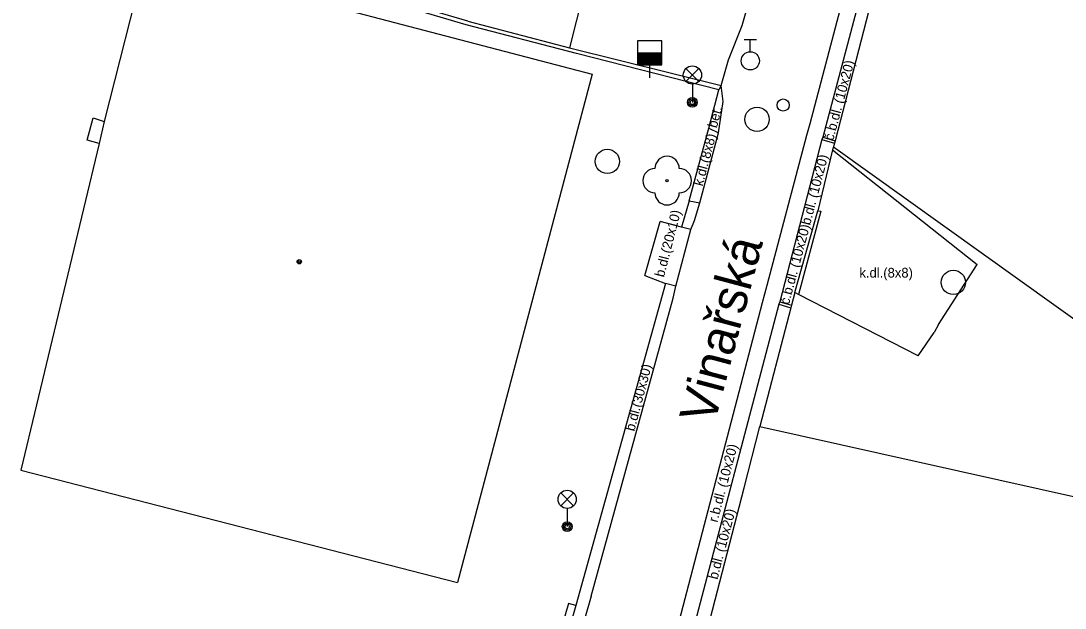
# Model space of a CAD drawing. Extents: x -600309 to -598967, y -1161267 to -1160292.
# Drawn here: x -600075.62 to -600032.67, y -1161065 to -1161040.84 of the extents above; entities that cross this region are included whole.
import ezdxf

# ---------------------------------------------------------------- set-up
doc = ezdxf.new("R2010")
doc.units = 0
for name, color, linetype in [('Level 10', 7, 'Continuous'), ('Level 11', 7, 'Continuous'), ('Level 22', 7, 'Continuous'), ('Level 24', 7, 'Continuous'), ('Level 27', 7, 'Continuous'), ('Level 28', 7, 'Continuous'), ('Level 31', 7, 'Continuous'), ('Level 33', 7, 'Continuous'), ('Level 39', 7, 'Continuous'), ('Level 40', 7, 'Continuous'), ('Level 5', 7, 'Continuous'), ('Level 50', 7, 'Continuous'), ('Level 51', 7, 'Continuous'), ('Level 7', 7, 'Continuous'), ('Level 8', 7, 'Continuous')]:
    doc.layers.add(name, color=color, linetype=linetype)

msp = doc.modelspace()

# ---------------------------------------------------------------- linework, layer by layer
at = {"layer": 'Level 10'}
for points in [[(-600049.36, -1161068.66), (-600048.8618, -1161066.7575), (-600045.11, -1161052.43), (-600044.93, -1161051.71), (-600043.29, -1161045.54), (-600043.16, -1161045.06), (-600039.19, -1161030.02), (-600039.02, -1161029.32), (-600036.88, -1161021.28), (-600036.71, -1161020.58), (-600034.3582, -1161011.7987), (-600029.87, -1160995.04), (-600029.54, -1160993.62), (-600029.33, -1160992.62)], [(-600052.17, -1161064.51), (-600048.79, -1161052.25), (-600048.68, -1161051.76), (-600048.06, -1161049.42), (-600047.92, -1161049.05), (-600047.69, -1161048.32), (-600046.93, -1161045.44), (-600046.73, -1161044.16), (-600046.82, -1161043.5), (-600046.51, -1161042.44), (-600045.95, -1161041.02), (-600045.06, -1161037.91), (-600044.82, -1161036.91)], [(-600052.17, -1161064.51), (-600054.64, -1161073.14)]]:
    msp.add_lwpolyline(points, dxfattribs=at)
at = {"layer": 'Level 11'}
for points in [[(-600028.23, -1160992.86), (-600028.68, -1160992.75), (-600028.95, -1160993.92), (-600029.25, -1160995.22), (-600036.2, -1161021.2), (-600036.23, -1161021.3), (-600038.47, -1161029.88), (-600038.5, -1161029.98), (-600042.64, -1161045.62), (-600042.67, -1161045.72), (-600044.41, -1161052.4), (-600044.44, -1161052.5), (-600048.21, -1161066.82)], [(-600057.24, -1161040.85), (-600063.37, -1161039.04), (-600073.51, -1161036.42), (-600073.55, -1161036.53)], [(-600057.24, -1161040.85), (-600053.05, -1161041.95)], [(-600053.05, -1161041.95), (-600046.82, -1161043.5)], [(-600046.82, -1161043.5), (-600046.91, -1161043.67)], [(-600072.89, -1161045.75), (-600072.65, -1161044.83)], [(-600072.65, -1161044.83), (-600072.2, -1161044.98)], [(-600047.33, -1161045.25), (-600046.93, -1161045.44)], [(-600072.4, -1161045.88), (-600072.89, -1161045.75)], [(-600042.67, -1161045.72), (-600042.16, -1161045.87)], [(-600042.64, -1161045.62), (-600042.13, -1161045.77)], [(-600042.24, -1161046.14), (-600042.84, -1161048.65)], [(-600048.13, -1161048.24), (-600047.69, -1161048.32)], [(-600048.06, -1161049.42), (-600048.45, -1161049.32)], [(-600048.68, -1161051.76), (-600049.11, -1161051.64)], [(-600044.44, -1161052.5), (-600043.95, -1161052.64)], [(-600044.41, -1161052.4), (-600043.92, -1161052.54)]]:
    msp.add_lwpolyline(points, dxfattribs=at)
at = {"layer": 'Level 22'}
msp.add_circle((-600049.04, -1161047.4099), 0.05, dxfattribs=at)
for centre, start, end in [((-600049.04, -1161046.9099), 0, 180), ((-600049.54, -1161047.4099), 90, 270), ((-600048.54, -1161047.4099), 270, 90), ((-600049.04, -1161047.9099), 180, 0)]:
    msp.add_arc(centre, 0.5, start, end, dxfattribs=at)
at = {"layer": 'Level 24'}
for points in [[(-600043.79, -1161052.02), (-600042.84, -1161048.65)], [(-600042.84, -1161048.65), (-600042.72, -1161048.67), (-600043.63, -1161052.1)]]:
    msp.add_lwpolyline(points, dxfattribs=at)
at = {"layer": 'Level 27'}
for centre in [(-600045.34, -1161044.89), (-600051.5, -1161046.62), (-600037.27, -1161051.6)]:
    msp.add_circle(centre, 0.5, dxfattribs=at)
at = {"layer": 'Level 28'}
for p, q in [((-600045.87, -1161041.605), (-600045.37, -1161041.605)), ((-600045.62, -1161042.105), (-600045.62, -1161041.605)), ((-600050.26, -1161042.15), (-600049.26, -1161042.15)), ((-600050.26, -1161042.2), (-600049.26, -1161042.2)), ((-600050.26, -1161042.25), (-600049.26, -1161042.25)), ((-600050.26, -1161042.3), (-600049.26, -1161042.3)), ((-600050.26, -1161042.35), (-600049.26, -1161042.35)), ((-600050.26, -1161042.4), (-600049.26, -1161042.4)), ((-600050.26, -1161042.45), (-600049.26, -1161042.45)), ((-600050.26, -1161042.5), (-600049.26, -1161042.5)), ((-600050.26, -1161042.55), (-600049.26, -1161042.55)), ((-600050.26, -1161042.6), (-600049.26, -1161042.6)), ((-600049.76, -1161042.65), (-600049.76, -1161043.18))]:
    msp.add_line(p, q, dxfattribs=at)
msp.add_lwpolyline([(-600050.26, -1161042.65), (-600049.26, -1161042.65), (-600049.26, -1161041.65), (-600050.26, -1161041.65)], close=True, dxfattribs=at)
msp.add_circle((-600045.62, -1161042.48), 0.375, dxfattribs=at)
at = {"layer": 'Level 31'}
msp.add_circle((-600044.27, -1161044.3), 0.25, dxfattribs=at)
at = {"layer": 'Level 33'}
for p, q in [((-600048.265, -1161043.33), (-600047.735, -1161042.8)), ((-600048.265, -1161042.8), (-600047.735, -1161043.33)), ((-600048, -1161043.44), (-600048, -1161044.19)), ((-600053.415, -1161060.79), (-600052.885, -1161060.26)), ((-600053.415, -1161060.26), (-600052.885, -1161060.79)), ((-600053.15, -1161060.9), (-600053.15, -1161061.65))]:
    msp.add_line(p, q, dxfattribs=at)
for centre, radius in [((-600048, -1161043.065), 0.375), ((-600048, -1161044.19), 0.2), ((-600048, -1161044.19), 0.1445), ((-600048, -1161044.19), 0.0876), ((-600053.15, -1161060.525), 0.375), ((-600053.15, -1161061.65), 0.2), ((-600053.15, -1161061.65), 0.1445), ((-600053.15, -1161061.65), 0.0876)]:
    msp.add_circle(centre, radius, dxfattribs=at)
at = {"layer": 'Level 39'}
for radius in [0.09, 0.0398]:
    msp.add_circle((-600064.17, -1161050.75), radius, dxfattribs=at)
at = {"layer": 'Level 5'}
for points in [[(-600070.48, -1161038.21), (-600072.2, -1161044.98)], [(-600070.48, -1161038.21), (-600052.12, -1161043.03)], [(-600052.12, -1161043.03), (-600057.6599, -1161063.95)], [(-600072.2, -1161044.98), (-600072.4, -1161045.88)], [(-600072.4, -1161045.88), (-600075.62, -1161059.32)], [(-600075.62, -1161059.32), (-600057.6599, -1161063.95)]]:
    msp.add_lwpolyline(points, dxfattribs=at)
at = {"layer": 'Level 51'}
for points in [[(-600042.2, -1161046.02), (-600026.96, -1161056.92)], [(-600045.2199, -1161057.53), (-600027.23, -1161061.55)]]:
    msp.add_lwpolyline(points, dxfattribs=at)
at = {"layer": 'Level 7'}
for points in [[(-600037.9, -1161029.49), (-600038.05, -1161029.99), (-600038.08, -1161030.09), (-600042.13, -1161045.77), (-600042.16, -1161045.87), (-600042.2, -1161046.02), (-600042.24, -1161046.14)], [(-600052.77, -1161042.18), (-600057.3, -1161041), (-600063.39, -1161039.19)], [(-600046.91, -1161043.67), (-600052.77, -1161042.18)], [(-600047.33, -1161045.25), (-600046.91, -1161043.67)], [(-600048.13, -1161048.24), (-600047.33, -1161045.25)], [(-600042.24, -1161046.14), (-600036.29, -1161050.86)], [(-600048.13, -1161048.24), (-600048.45, -1161049.32), (-600049.33, -1161049.09)], [(-600049.95, -1161051.32), (-600049.11, -1161051.64), (-600052.79, -1161064.9)], [(-600043.79, -1161052.02), (-600043.92, -1161052.54), (-600043.95, -1161052.64)], [(-600038.71, -1161054.62), (-600043.63, -1161052.1), (-600043.79, -1161052.02)], [(-600043.95, -1161052.64), (-600045.22, -1161057.53)], [(-600037.88, -1161053.33), (-600038.05, -1161053.66)], [(-600045.87, -1161060.06), (-600045.2199, -1161057.53)], [(-600048.1599, -1161068.86), (-600047.7, -1161067.09), (-600047.67, -1161066.99), (-600045.87, -1161060.06)], [(-600052.79, -1161064.9), (-600055.12, -1161073.03), (-600057.12, -1161080.03)], [(-600053.09, -1161064.82), (-600055.76, -1161074.01)], [(-600052.79, -1161064.9), (-600053.09, -1161064.82)]]:
    msp.add_lwpolyline(points, dxfattribs=at)
at = {"layer": 'Level 8'}
for points in [[(-600051.91, -1161037.37), (-600053.05, -1161041.95)], [(-600049.95, -1161051.32), (-600049.33, -1161049.09)], [(-600037.88, -1161053.33), (-600036.29, -1161050.86)], [(-600038.71, -1161054.62), (-600038.05, -1161053.66)]]:
    msp.add_lwpolyline(points, dxfattribs=at)

# ---------------------------------------------------------------- texts
at = {"layer": 'Level 40'}
for s, rotation, p in [('č.b.dl. (10x20)', 75.01, (-600042.21, -1161045.79)), ('bet.', 75, (-600047, -1161045.27)), ('k.dl.(8x8)', 75.22, (-600047.58, -1161047.66)), ('b.dl. (10x20)', 75.37, (-600043.16, -1161049.27)), ('b.dl.(20x10)', 75.61, (-600049.17, -1161051.41)), ('č.b.dl. (10x20)', 75.01, (-600044.03, -1161052.54)), ('b.dl.(30x30)', 75.16, (-600050.39, -1161057.75)), ('r.b.dl. (10x20)', 75.37, (-600046.97, -1161061.5)), ('b.dl. (10x20)', 75.37, (-600046.97, -1161063.85))]:
    msp.add_text(s, height=0.4, rotation=rotation, dxfattribs=at).set_placement(p)
msp.add_text('k.dl.(8x8)', height=0.4, dxfattribs=at).set_placement((-600041.13, -1161051.4))
at = {"layer": 'Level 50'}
msp.add_text('Vinařská', height=1.5, rotation=75.0861, dxfattribs=at).set_placement((-600047.1018, -1161057.491))

doc.saveas('drawing.dxf')
